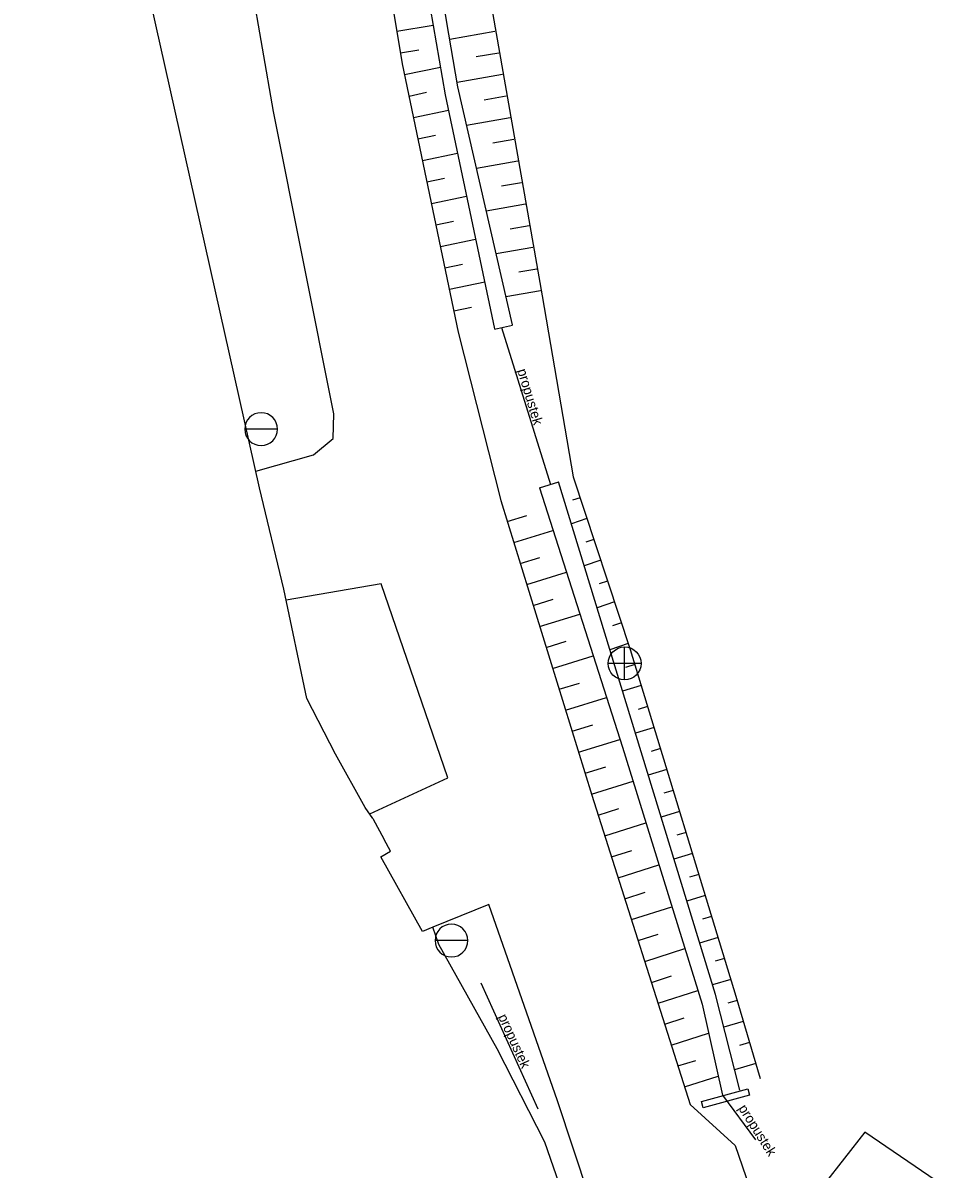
# Model space of a CAD drawing. Extents: x -747135 to -746147, y -1093269 to -1091735.
# Drawn here: x -746640.6 to -746599, y -1092863.2 to -1092810.9 of the extents above; entities that cross this region are included whole.
import ezdxf

# ---------------------------------------------------------------- set-up
doc = ezdxf.new("R2010")
doc.units = 0
for name, color, linetype in [('101', 7, 'Continuous'), ('1016', 7, 'Continuous'), ('105', 7, 'Continuous'), ('23700', 7, 'Continuous'), ('305', 7, 'Continuous'), ('316', 7, 'Continuous'), ('803', 7, 'Continuous')]:
    doc.layers.add(name, color=color, linetype=linetype)

msp = doc.modelspace()

# ---------------------------------------------------------------- linework, layer by layer
at = {"layer": '101'}
for points in [[(-746626.71, -1092783.97), (-746625.36, -1092789.94), (-746623.69, -1092800.76), (-746621.37, -1092814.2), (-746619.121, -1092824.876)], [(-746618.309, -1092824.695), (-746620.8, -1092813.84), (-746621.31, -1092810.82), (-746622.95, -1092800.4), (-746624.71, -1092789.67), (-746624.97, -1092783.83)], [(-746623.571, -1092811.311), (-746621.916, -1092811.038)], [(-746619.108, -1092811.316), (-746621.165, -1092811.678)], [(-746623.408, -1092812.298), (-746622.577, -1092812.161)], [(-746618.935, -1092812.3), (-746619.967, -1092812.482)], [(-746623.224, -1092813.281), (-746621.588, -1092812.939)], [(-746618.761, -1092813.285), (-746620.832, -1092813.65)], [(-746623.02, -1092814.26), (-746622.219, -1092814.092)], [(-746618.588, -1092814.27), (-746619.604, -1092814.449)], [(-746622.816, -1092815.239), (-746621.221, -1092814.906)], [(-746618.415, -1092815.255), (-746620.395, -1092815.604)], [(-746622.612, -1092816.217), (-746621.814, -1092816.051)], [(-746618.241, -1092816.24), (-746619.206, -1092816.41)], [(-746622.408, -1092817.196), (-746620.809, -1092816.863)], [(-746618.068, -1092817.225), (-746619.947, -1092817.556)], [(-746622.204, -1092818.175), (-746621.403, -1092818.008)], [(-746617.894, -1092818.21), (-746618.809, -1092818.371)], [(-746622, -1092819.154), (-746620.397, -1092818.82)], [(-746617.721, -1092819.194), (-746619.499, -1092819.508)], [(-746621.796, -1092820.133), (-746620.993, -1092819.966)], [(-746617.547, -1092820.179), (-746618.411, -1092820.331)], [(-746621.591, -1092821.112), (-746619.985, -1092820.777)], [(-746617.374, -1092821.164), (-746619.052, -1092821.46)], [(-746621.387, -1092822.091), (-746620.583, -1092821.923)], [(-746617.201, -1092822.149), (-746618.014, -1092822.292)], [(-746621.183, -1092823.07), (-746619.572, -1092822.734)], [(-746617.027, -1092823.134), (-746618.604, -1092823.411)], [(-746620.979, -1092824.049), (-746620.173, -1092823.881)], [(-746607.95, -1092859.56), (-746609.06, -1092855.21), (-746612.68, -1092843.4), (-746616.204, -1092831.845)], [(-746617.084, -1092832.121), (-746613.3, -1092843.93), (-746609.67, -1092855.65), (-746608.74, -1092859.8)], [(-746615.226, -1092832.57), (-746615.57, -1092832.683)], [(-746618.545, -1092833.655), (-746617.656, -1092833.381)], [(-746614.913, -1092833.519), (-746615.622, -1092833.753)], [(-746618.25, -1092834.611), (-746616.463, -1092834.059)], [(-746614.599, -1092834.469), (-746614.965, -1092834.589)], [(-746617.954, -1092835.566), (-746617.056, -1092835.289)], [(-746614.285, -1092835.418), (-746615.038, -1092835.667)], [(-746617.659, -1092836.522), (-746615.852, -1092835.963)], [(-746613.972, -1092836.368), (-746614.359, -1092836.496)], [(-746617.364, -1092837.477), (-746616.456, -1092837.196)], [(-746613.658, -1092837.317), (-746614.455, -1092837.58)], [(-746617.069, -1092838.433), (-746615.242, -1092837.868)], [(-746613.344, -1092838.267), (-746613.754, -1092838.402)], [(-746616.773, -1092839.388), (-746615.855, -1092839.104)], [(-746613.03, -1092839.216), (-746613.871, -1092839.494)], [(-746616.478, -1092840.343), (-746614.632, -1092839.773)], [(-746612.733, -1092840.171), (-746613.159, -1092840.301)], [(-746616.183, -1092841.299), (-746615.255, -1092841.012)], [(-746612.441, -1092841.127), (-746613.294, -1092841.387)], [(-746615.888, -1092842.254), (-746614.022, -1092841.678)], [(-746612.15, -1092842.084), (-746612.576, -1092842.214)], [(-746615.592, -1092843.21), (-746614.654, -1092842.92)], [(-746611.858, -1092843.041), (-746612.71, -1092843.3)], [(-746615.297, -1092844.165), (-746613.411, -1092843.582)], [(-746611.567, -1092843.997), (-746611.992, -1092844.127)], [(-746615.002, -1092845.121), (-746614.057, -1092844.829)], [(-746611.276, -1092844.954), (-746612.124, -1092845.212)], [(-746614.707, -1092846.076), (-746612.816, -1092845.492)], [(-746610.984, -1092845.91), (-746611.408, -1092846.039)], [(-746614.404, -1092847.029), (-746613.465, -1092846.73)], [(-746610.693, -1092846.867), (-746611.538, -1092847.125)], [(-746614.101, -1092847.982), (-746612.229, -1092847.387)], [(-746610.401, -1092847.824), (-746610.823, -1092847.952)], [(-746613.798, -1092848.935), (-746612.866, -1092848.639)], [(-746610.11, -1092848.78), (-746610.952, -1092849.037)], [(-746613.495, -1092849.888), (-746611.638, -1092849.297)], [(-746609.819, -1092849.737), (-746610.239, -1092849.865)], [(-746613.192, -1092850.841), (-746612.267, -1092850.547)], [(-746609.527, -1092850.693), (-746610.366, -1092850.949)], [(-746612.889, -1092851.794), (-746611.046, -1092851.208)], [(-746609.236, -1092851.65), (-746609.654, -1092851.777)], [(-746612.586, -1092852.747), (-746611.668, -1092852.455)], [(-746608.944, -1092852.607), (-746609.78, -1092852.861)], [(-746612.283, -1092853.7), (-746610.454, -1092853.118)], [(-746608.653, -1092853.563), (-746609.07, -1092853.69)], [(-746611.98, -1092854.653), (-746611.069, -1092854.363)], [(-746608.362, -1092854.52), (-746609.194, -1092854.773)], [(-746611.677, -1092855.606), (-746609.862, -1092855.029)], [(-746608.072, -1092855.477), (-746608.5, -1092855.602)], [(-746611.374, -1092856.559), (-746610.484, -1092856.276)], [(-746607.791, -1092856.437), (-746608.68, -1092856.698)], [(-746611.071, -1092857.512), (-746609.374, -1092856.972)], [(-746607.509, -1092857.396), (-746607.971, -1092857.532)], [(-746610.768, -1092858.465), (-746609.961, -1092858.208)], [(-746607.228, -1092858.356), (-746608.186, -1092858.637)], [(-746610.465, -1092859.418), (-746608.935, -1092858.931)]]:
    msp.add_lwpolyline(points, dxfattribs=at)
at = {"layer": '1016'}
for points in [[(-746627.15, -1092784.02), (-746627.36, -1092786.44), (-746626.8, -1092790.33), (-746625.27, -1092801.07), (-746623.33, -1092812.79), (-746620.78, -1092825.03)], [(-746630, -1092831.35), (-746627.38, -1092830.62), (-746626.48, -1092829.87), (-746626.44, -1092828.74), (-746629.2, -1092814.96), (-746631.2, -1092803.41), (-746631.6, -1092801.51)], [(-746620.78, -1092825.03), (-746618.84, -1092832.7)], [(-746618.84, -1092832.7), (-746614.69, -1092846.13), (-746610.21, -1092860.22)], [(-746624.8, -1092846.98), (-746621.26, -1092845.34), (-746624.29, -1092836.49), (-746628.62, -1092837.24)], [(-746604.94, -1092923.82), (-746603.73, -1092922.94), (-746602.98, -1092921.58), (-746602.37, -1092919.14), (-746601.93, -1092916.74), (-746601.75, -1092914.6), (-746601.83, -1092911.07), (-746602.53, -1092905.39), (-746603.47, -1092900.25), (-746604.79, -1092895.49), (-746611.22, -1092875.29), (-746616.25, -1092860.06), (-746619.38, -1092851.1), (-746621.94, -1092852.14)], [(-746609.69, -1092860.09), (-746607.59, -1092859.5), (-746607.51, -1092859.789), (-746609.62, -1092860.37), (-746609.69, -1092860.09)], [(-746610.21, -1092860.22), (-746608.17, -1092862.09), (-746607.01, -1092865.45), (-746607.57, -1092867.92), (-746606.89, -1092870.07)], [(-746599.01, -1092863.7), (-746602.25, -1092861.48), (-746604.11, -1092863.85), (-746603.71, -1092864.86), (-746604.95, -1092866.72), (-746602.58, -1092868.51)]]:
    msp.add_lwpolyline(points, dxfattribs=at)
at = {"layer": '23700'}
for points in [[(-746618.81, -1092824.81), (-746616.58, -1092831.96)], [(-746617.13, -1092860.43), (-746619.73, -1092854.69)], [(-746608.74, -1092859.8), (-746607.23, -1092861.83)]]:
    msp.add_lwpolyline(points, dxfattribs=at)
at = {"layer": '305'}
for points in [[(-746616.96, -1092823.36), (-746615.54, -1092831.62)], [(-746628.73, -1092836.73), (-746629.83, -1092832.11)], [(-746624.67, -1092847.18), (-746624.15, -1092848.15)], [(-746622.4, -1092852.33), (-746624.3, -1092848.94)]]:
    msp.add_lwpolyline(points, dxfattribs=at)
at = {"layer": '316'}
for p, q in [((-746629.013, -1092829.44), (-746630.508, -1092829.44)), ((-746613.201, -1092840.868), (-746613.2, -1092839.373)), ((-746612.448, -1092840.126), (-746613.948, -1092840.121)), ((-746620.343, -1092852.75), (-746621.838, -1092852.75))]:
    msp.add_line(p, q, dxfattribs=at)
msp.add_circle((-746613.2, -1092840.12), 0.75, dxfattribs=at)
for centre, start, end in [((-746629.76, -1092829.44), 0, 180), ((-746629.76, -1092829.44), 180, 0), ((-746621.09, -1092852.75), 0, 180), ((-746621.09, -1092852.75), 180, 0)]:
    msp.add_arc(centre, 0.747, start, end, dxfattribs=at)
at = {"layer": '803'}
for points in [[(-746624.2, -1092782.38), (-746620.59, -1092802.65), (-746616.96, -1092823.36)], [(-746629.83, -1092832.11), (-746635.92, -1092804.9), (-746640.61, -1092805.95)], [(-746619.12, -1092824.88), (-746618.31, -1092824.7)], [(-746617.08, -1092832.12), (-746616.2, -1092831.85)], [(-746615.54, -1092831.62), (-746612.94, -1092839.49), (-746608.13, -1092855.28), (-746607.03, -1092859.03)], [(-746627.68, -1092841.72), (-746628.73, -1092836.73)], [(-746626.37, -1092844.26), (-746627.68, -1092841.72)], [(-746625.02, -1092846.68), (-746626.37, -1092844.26)], [(-746624.67, -1092847.18), (-746625.02, -1092846.68)], [(-746624.3, -1092848.94), (-746623.87, -1092848.67), (-746624.15, -1092848.15)], [(-746621.66, -1092852.93), (-746621.94, -1092852.14), (-746622.4, -1092852.33)], [(-746605.5, -1092896.5), (-746612.2, -1092875.87), (-746615.13, -1092866.85), (-746616.83, -1092861.94), (-746619, -1092857.68), (-746621.66, -1092852.93)]]:
    msp.add_lwpolyline(points, dxfattribs=at)

# ---------------------------------------------------------------- texts
at = {"layer": '105'}
for rotation, p in [(286.5409, (-746618.091, -1092826.76)), (294.4001, (-746618.969, -1092856.215)), (302.2556, (-746608.034, -1092860.391))]:
    msp.add_text('propustek', height=0.45, rotation=rotation, dxfattribs=at).set_placement(p)

doc.saveas('drawing.dxf')
